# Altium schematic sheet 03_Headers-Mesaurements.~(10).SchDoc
size A4; SheetNumber: 3; SheetTotal: 2
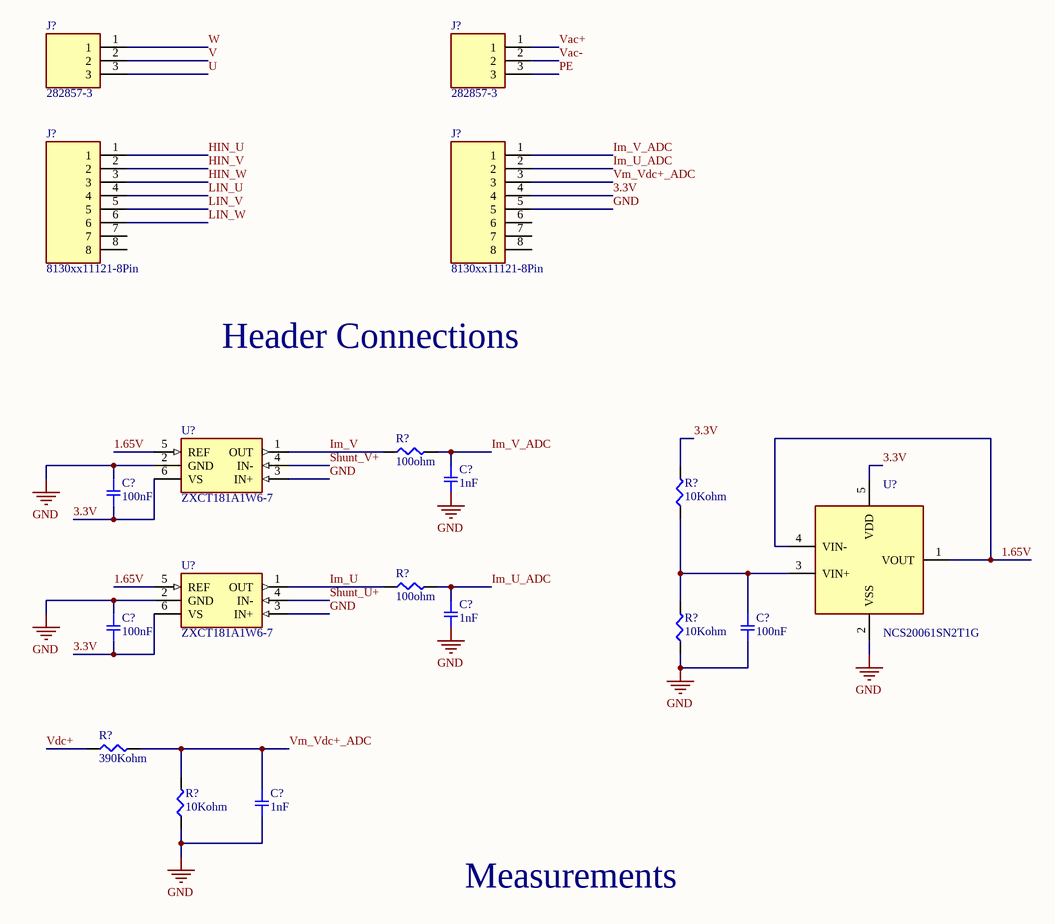
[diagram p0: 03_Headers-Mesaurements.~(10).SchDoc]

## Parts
(Parts that share a designator on the sheet are numbered #1, #2 ... from top to bottom, then left to right.)
C?#1  1nF  [006_SMD_0605]
C?#2  100nF  [006_SMD_0605]
C?#3  1nF  [006_SMD_0605]
C?#4  100nF  [006_SMD_0605]
C?#5  100nF  [001_SMD-1206]
C?#6  1nF  [006_SMD_0605]
J?#1  282857-3  [201_TE_282857-3]
J?#2  282857-3  [201_TE_282857-3]
J?#3  8130xx11121-8Pin  [200_HDRV6W64P0X254_1X6_1524X254X869P]
J?#4  8130xx11121-8Pin  [200_HDRV6W64P0X254_1X6_1524X254X869P]
R?#1  100ohm  [006_SMD_0605]
R?#2  10Kohm  [001_SMD-1206]
R?#3  100ohm  [006_SMD_0605]
R?#4  10Kohm  [001_SMD-1206]
R?#5  390Kohm  [001_SMD-1206]
R?#6  10Kohm  [001_SMD-1206]
U?#1  ZXCT181A1W6-7  [896_ZXCT181A1W6-7]
U?#2  NCS20061SN2T1G  [897_NCS20061SN2T1G]
U?#3  ZXCT181A1W6-7  [896_ZXCT181A1W6-7]

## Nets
GND: C?#1.2 C?#2.1 C?#3.2 C?#4.1 C?#5.2 C?#6.2 J?#4.5 R?#4.1 R?#6.1 U?#1.2(GND) U?#1.3(IN+) U?#2.2(VSS) U?#3.2(GND) U?#3.3(IN+)
1.65V: U?#1.5(REF) U?#2.1(VOUT) U?#2.4(VIN-) U?#3.5(REF)
3.3V: C?#2.2 C?#4.2 J?#4.4 R?#2.2 U?#1.6(VS) U?#2.5(VDD) U?#3.6(VS)
HIN_U: J?#3.1
HIN_V: J?#3.2
HIN_W: J?#3.3
Im_U: R?#3.1 U?#3.1(OUT)
Im_U_ADC: C?#3.1 J?#4.2 R?#3.2
Im_V: R?#1.1 U?#1.1(OUT)
Im_V_ADC: C?#1.1 J?#4.1 R?#1.2
LIN_U: J?#3.4
LIN_V: J?#3.5
LIN_W: J?#3.6
PE: J?#2.3
Shunt_U+: U?#3.4(IN-)
Shunt_V+: U?#1.4(IN-)
U: J?#1.3
V: J?#1.2
Vac+: J?#2.1
Vac-: J?#2.2
Vdc+: R?#5.1
Vm_Vdc+_ADC: C?#6.1 J?#4.3 R?#5.2 R?#6.2
W: J?#1.1
NetC?#5_1: C?#5.1 R?#2.1 R?#4.2 U?#2.3(VIN+)

Not connected (* = marked no-connect by the designer): J?#3 7 8; J?#4 6 7 8

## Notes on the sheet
- Header Connections
- Measurements

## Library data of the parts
C?#1-C?#4 C?#6 = C_0605_Template: CAP CER 0605; Part Number: GC321AD72E103KX01D; Manufacturer: Murata Electronics North America; Factory Stock: 0; Unit Price (USD): 0.3; Minimum Quantity: 1; Value: 10000pF; Tolerance: ±10%; Voltage: 250V; Temperature Coefficient: X7T
C?#5 = C_1206_Template: CAP CER 1206; Part Number: GC321AD72E103KX01D; Manufacturer: Murata Electronics North America; Factory Stock: 0; Unit Price (USD): 0.3; Minimum Quantity: 1; Value: 10000pF; Tolerance: ±10%; Voltage: 250V; Temperature Coefficient: X7T
J?#1 J?#2 = 282857-3: 3 Position Wire to Board Terminal Block Horizontal with Board 0.200 (5.08mm) Through Hole; MF: TE Connectivity
J?#3 J?#4 = 6130xx11121-6Pin: 2.54MM PIN HEADER; Manufacturer_Name: Wurth Elektronik; Geometry.Height: 8.69mm
R?#1 R?#3 = R_0605_Template: RES SMD 0605; Part Number: ERJ-6BQF1R0V; Manufacturer: Panasonic Electronic Components; Factory Stock: 0; Unit Price (USD): 0.05834; @ qty: 1500; Minimum Quantity: 1; Value: 1; Tolerance: ±1%; Power (Watts): 0.333W, 1/3W; Temperature Coefficient: ±200ppm/°C
R?#2 R?#4-R?#6 = R_1206_Template: RES SMD 1206; Part Number: ERJ-8BQF1R0V; Manufacturer: Panasonic Electronic Components; Factory Stock: 0; Unit Price (USD): 0.05778; @ qty: 1500; Minimum Quantity: 1; Value: 1; Tolerance: ±1%; Power (Watts): 0.5W, 1/2W; Temperature Coefficient: ±200ppm/°C
U?#1 U?#3 = ZXCT181A1W6-7: Bidirectional high-side current-sense amplifier, fixed gain 20 V/V, 2.7–5.5 V supply, up to 26 V common-mode input range, SOT-26 package.; MF: Texas Instruments; MP: INA181A1IDBVR
U?#2 = NCS20061SN2T1G: Single, rail-to-rail operational amplifier used as a voltage buffer for the 1.65 V current-sense reference.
